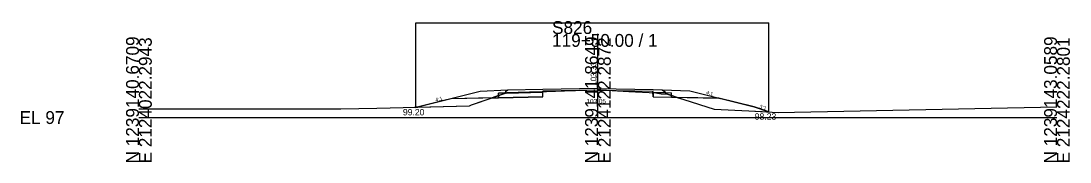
# Model space of a CAD drawing. Extents: x 2119282 to 2119710, y 1215030 to 1220057.
# Drawn here: x 2119381.9 to 2119610.4, y 1218030.1 to 1218060.9 of the extents above; entities that cross this region are included whole.
import ezdxf

# ---------------------------------------------------------------- set-up
doc = ezdxf.new("R2010")
doc.units = 0
for name, color, linetype in [('XS_CELL', 7, 'Continuous'), ('XS_M_DITCH', 7, 'Continuous'), ('XS_M_SHAPES_EARTHWORK', 7, 'Continuous'), ('XS_P_FINISHED_GRADE', 7, 'Continuous'), ('XS_P_FINISHED_GRADE_ELEV_TX', 7, 'Continuous'), ('XS_P_SUBGRADE_GRANULAR', 7, 'Continuous'), ('XS_P_SUBGRADE_PAVEMENT', 7, 'Continuous'), ('XS_P_TX_DCH', 7, 'Continuous'), ('XS_P_TX_FS_BS', 7, 'Continuous'), ('XS_X_GROUND', 7, 'Continuous'), ('XS_X_GROUND_TX', 7, 'Continuous')]:
    doc.layers.add(name, color=color, linetype=linetype)

msp = doc.modelspace()

# ---------------------------------------------------------------- linework, layer by layer
at = {"layer": 'XS_CELL'}
for p, q in [((2119507.6, 1218039.8), (2119507.6, 1218058.02)), ((2119407.6, 1218039.8), (2119507.6, 1218039.8)), ((2119507.6, 1218039.8), (2119607.6, 1218039.8))]:
    msp.add_line(p, q, dxfattribs=at)
at = {"layer": 'XS_M_DITCH'}
for p, q in [((2119467.96, 1218042), (2119467.96, 1218060.42)), ((2119467.96, 1218060.42), (2119544.83, 1218060.42)), ((2119544.83, 1218041.04), (2119544.83, 1218060.42))]:
    msp.add_line(p, q, dxfattribs=at)
at = {"layer": 'XS_M_SHAPES_EARTHWORK'}
for p, q in [((2119485.96, 1218044.58), (2119484.54, 1218044.09)), ((2119487.63, 1218045.15), (2119485.96, 1218044.58)), ((2119485.96, 1218044.58), (2119485.96, 1218044.12)), ((2119485.96, 1218044.12), (2119485.96, 1218044.58)), ((2119487.63, 1218045.15), (2119495.6, 1218045.31)), ((2119495.6, 1218045.31), (2119487.63, 1218045.15)), ((2119487.67, 1218045.16), (2119487.63, 1218045.15)), ((2119492.68, 1218045.33), (2119487.67, 1218045.16)), ((2119495.6, 1218045.44), (2119492.68, 1218045.33)), ((2119495.6, 1218045.31), (2119495.6, 1218045.44)), ((2119495.6, 1218044.31), (2119495.6, 1218045.31)), ((2119520.24, 1218045.16), (2119519.6, 1218045.2)), ((2119519.6, 1218045.2), (2119519.6, 1218044.31)), ((2119521.34, 1218045.01), (2119520.24, 1218045.16)), ((2119522.73, 1218044.9), (2119521.34, 1218045.01)), ((2119523.6, 1218044.61), (2119522.73, 1218044.9)), ((2119523.6, 1218044.23), (2119523.6, 1218044.61)), ((2119524.84, 1218044.2), (2119523.6, 1218044.61)), ((2119523.6, 1218044.61), (2119523.6, 1218044.23)), ((2119475.6, 1218043.91), (2119468.37, 1218042.1)), ((2119468.37, 1218042.1), (2119479.6, 1218042.38)), ((2119484.54, 1218044.09), (2119475.6, 1218043.91)), ((2119479.6, 1218042.38), (2119480.06, 1218042.55)), ((2119480.06, 1218042.55), (2119484.54, 1218044.09)), ((2119484.54, 1218044.09), (2119485.96, 1218044.12)), ((2119485.96, 1218044.12), (2119495.6, 1218044.31)), ((2119519.6, 1218044.31), (2119523.6, 1218044.23)), ((2119523.6, 1218044.23), (2119524.84, 1218044.2)), ((2119533.97, 1218044.02), (2119524.84, 1218044.2)), ((2119524.84, 1218044.2), (2119526.3, 1218043.73)), ((2119526.3, 1218043.73), (2119532.89, 1218041.62)), ((2119541.6, 1218042.11), (2119533.97, 1218044.02)), ((2119468.37, 1218042.1), (2119467.71, 1218042.08)), ((2119467.71, 1218042.08), (2119467.96, 1218042)), ((2119467.96, 1218042), (2119468.37, 1218042.1)), ((2119532.89, 1218041.62), (2119540.44, 1218041.28)), ((2119540.44, 1218041.28), (2119544.83, 1218041.04)), ((2119544.83, 1218041.04), (2119541.6, 1218042.11))]:
    msp.add_line(p, q, dxfattribs=at)
at = {"layer": 'XS_P_FINISHED_GRADE'}
for p, q in [((2119481.96, 1218045.5), (2119467.96, 1218042)), ((2119487.96, 1218045.74), (2119481.96, 1218045.5)), ((2119495.6, 1218045.89), (2119487.96, 1218045.74)), ((2119507.6, 1218046.13), (2119495.6, 1218045.89)), ((2119507.6, 1218046.13), (2119519.6, 1218045.89)), ((2119519.6, 1218045.89), (2119521.6, 1218045.85)), ((2119521.6, 1218045.85), (2119527.6, 1218045.61)), ((2119527.6, 1218045.61), (2119541.6, 1218042.11)), ((2119467.96, 1218042), (2119467.71, 1218042.08)), ((2119541.6, 1218042.11), (2119544.83, 1218041.04))]:
    msp.add_line(p, q, dxfattribs=at)
at = {"layer": 'XS_P_SUBGRADE_GRANULAR'}
for p, q in [((2119487.31, 1218045.14), (2119485.96, 1218045.09)), ((2119485.96, 1218044.12), (2119485.96, 1218045.09)), ((2119495.6, 1218044.31), (2119495.61, 1218045.31)), ((2119519.6, 1218044.31), (2119519.59, 1218045.31)), ((2119522.26, 1218045.26), (2119523.6, 1218045.2)), ((2119523.6, 1218044.23), (2119523.6, 1218045.2)), ((2119485.96, 1218044.12), (2119475.6, 1218043.91)), ((2119495.6, 1218044.31), (2119485.96, 1218044.12)), ((2119519.6, 1218044.31), (2119523.6, 1218044.23)), ((2119523.6, 1218044.23), (2119533.97, 1218044.02))]:
    msp.add_line(p, q, dxfattribs=at)
at = {"layer": 'XS_P_SUBGRADE_PAVEMENT'}
for p, q in [((2119487.46, 1218045.4), (2119487.31, 1218045.14)), ((2119495.61, 1218045.31), (2119487.31, 1218045.14)), ((2119487.96, 1218045.74), (2119487.46, 1218045.4)), ((2119507.6, 1218045.8), (2119495.61, 1218045.56)), ((2119495.61, 1218045.31), (2119495.61, 1218045.56)), ((2119507.6, 1218045.8), (2119519.6, 1218045.56)), ((2119519.59, 1218045.31), (2119519.6, 1218045.56)), ((2119519.59, 1218045.31), (2119522.26, 1218045.26)), ((2119521.6, 1218045.85), (2119522.11, 1218045.51)), ((2119522.11, 1218045.51), (2119522.26, 1218045.26))]:
    msp.add_line(p, q, dxfattribs=at)
at = {"layer": 'XS_X_GROUND'}
for p, q in [((2119480.06, 1218042.55), (2119487.67, 1218045.16)), ((2119487.67, 1218045.16), (2119492.68, 1218045.33)), ((2119492.68, 1218045.33), (2119496.36, 1218045.47)), ((2119496.36, 1218045.47), (2119500.35, 1218045.61)), ((2119500.35, 1218045.61), (2119507.6, 1218045.85)), ((2119507.6, 1218045.85), (2119508.21, 1218045.87)), ((2119508.21, 1218045.87), (2119514.34, 1218045.5)), ((2119514.34, 1218045.5), (2119520.24, 1218045.16)), ((2119520.24, 1218045.16), (2119521.34, 1218045.01)), ((2119521.34, 1218045.01), (2119522.73, 1218044.9)), ((2119522.73, 1218044.9), (2119526.3, 1218043.73)), ((2119459.44, 1218041.88), (2119479.6, 1218042.38)), ((2119479.6, 1218042.38), (2119480.06, 1218042.55)), ((2119526.3, 1218043.73), (2119532.89, 1218041.62)), ((2119407.6, 1218041.67), (2119419.76, 1218041.69)), ((2119419.76, 1218041.69), (2119451.59, 1218041.74)), ((2119451.59, 1218041.74), (2119459.44, 1218041.88)), ((2119532.89, 1218041.62), (2119540.44, 1218041.28)), ((2119540.44, 1218041.28), (2119546.86, 1218040.92)), ((2119546.86, 1218040.92), (2119607.6, 1218042.13))]:
    msp.add_line(p, q, dxfattribs=at)

# ---------------------------------------------------------------- texts
at = {"layer": 'XS_CELL'}
for s, p in [('S826', (2119497.6, 1218058.02)), ('119+50.00 / 1', (2119497.6, 1218055.22)), ('EL 97', (2119381.6, 1218038.4))]:
    msp.add_text(s, height=2.8, dxfattribs=at).set_placement(p)
for s, p in [('N 1239140.6709', (2119407.6, 1218029.8)), ('E 2124022.2943', (2119410.4, 1218029.8)), ('N 1239141.8649', (2119507.6, 1218029.8)), ('E 2124122.2872', (2119510.4, 1218029.8)), ('N 1239143.0589', (2119607.6, 1218029.8)), ('E 2124222.2801', (2119610.4, 1218029.8))]:
    msp.add_text(s, height=2.8, rotation=90, dxfattribs=at).set_placement(p)
at = {"layer": 'XS_P_FINISHED_GRADE_ELEV_TX'}
msp.add_text('103.33', height=1.25, rotation=90, dxfattribs=at).set_placement((2119507.26, 1218046.8))
at = {"layer": 'XS_P_TX_DCH'}
for s, p in [('99.20', (2119465.12, 1218040.28)), ('98.23', (2119541.77, 1218039.33))]:
    msp.add_text(s, height=1.4, dxfattribs=at).set_placement(p)
at = {"layer": 'XS_P_TX_FS_BS'}
for s, rotation, p in [('4:1', 345.9638, (2119531.11, 1218044.91)), ('4:1', 14.0362, (2119472.31, 1218043.24)), ('3:1', 341.5651, (2119542.71, 1218041.89))]:
    msp.add_text(s, height=0.8, rotation=rotation, dxfattribs=at).set_placement(p)
at = {"layer": 'XS_X_GROUND_TX'}
msp.add_text('103.05', height=1, dxfattribs=at).set_placement((2119505.11, 1218042.86))

doc.saveas('drawing.dxf')
